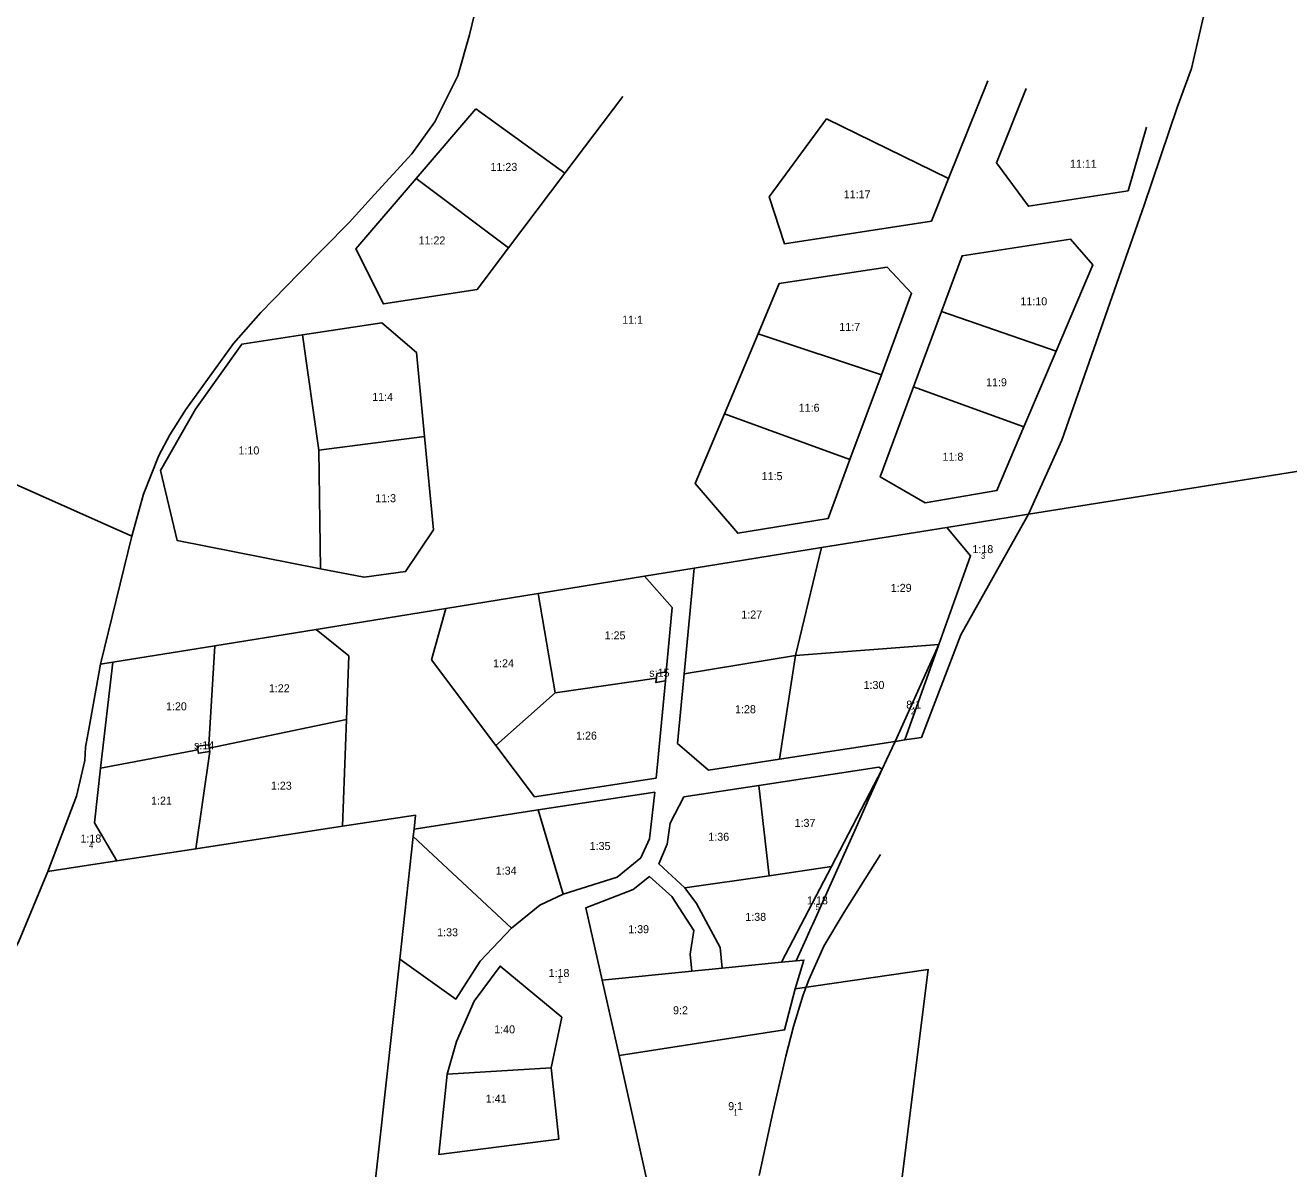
# Model space of a CAD drawing. Extents: x 140824 to 143748, y 6547319 to 6550906.
# Drawn here: x 142272 to 142825, y 6549186 to 6549686 of the extents above; entities that cross this region are included whole.
import ezdxf

# ---------------------------------------------------------------- set-up
doc = ezdxf.new("R2010")
doc.units = 0
for name, color, linetype in [('FAST Fastighetsgräns', 7, 'Continuous'), ('FAST Mittlinjeredovisad samfällighet', 7, 'Continuous'), ('FAST Områdesnummer för fastighet', 7, 'Continuous'), ('FAST Registernummer för fastighet', 7, 'Continuous'), ('FAST Registernummer för samfällighet', 7, 'Continuous'), ('FAST Traktgräns', 7, 'Continuous')]:
    doc.layers.add(name, color=color, linetype=linetype)

msp = doc.modelspace()

# ---------------------------------------------------------------- linework, layer by layer
at = {"layer": 'FAST Fastighetsgräns'}
for p, q in [((142675.82, 6549619.05), (142692.96, 6549661.84)), ((142508.04, 6549621.45), (142533.31, 6549654.96)), ((142469, 6549649.51), (142443, 6549619.12)), ((142469, 6549649.51), (142508.04, 6549621.45)), ((142622.4, 6549645.12), (142675.82, 6549619.05)), ((142483.42, 6549588.77), (142508.04, 6549621.45)), ((142443, 6549619.12), (142483.42, 6549588.77)), ((142672.7, 6549560.85), (142660.55, 6549527.94)), ((142672.7, 6549560.85), (142722.85, 6549543.49)), ((142400.45, 6549500.17), (142393.31, 6549550.62)), ((142592.5, 6549551.11), (142577.8, 6549516.08)), ((142592.5, 6549551.11), (142646.45, 6549533.24)), ((142708.8, 6549510.39), (142722.85, 6549543.49)), ((142632.71, 6549496.13), (142646.45, 6549533.24)), ((142660.55, 6549527.94), (142708.8, 6549510.39)), ((142577.8, 6549516.08), (142632.71, 6549496.13)), ((142446.62, 6549506.21), (142400.45, 6549500.17)), ((142400.45, 6549500.17), (142401.09, 6549448.37)), ((142675.03, 6549466.45), (142710.83, 6549472.25)), ((142620.32, 6549457.6), (142675.03, 6549466.45)), ((142564.58, 6549448.57), (142620.32, 6549457.6)), ((142620.32, 6549457.6), (142608.93, 6549410.36)), ((142496.26, 6549437.52), (142542.85, 6549445.06)), ((142542.85, 6549445.06), (142564.58, 6549448.57)), ((142564.58, 6549448.57), (142560.21, 6549402.42)), ((142455.97, 6549431.01), (142496.26, 6549437.52)), ((142496.26, 6549437.52), (142503.8, 6549394.01)), ((142399.21, 6549421.82), (142455.97, 6549431.01)), ((142354.84, 6549414.65), (142399.21, 6549421.82)), ((142310.22, 6549407.43), (142354.84, 6549414.65)), ((142354.84, 6549414.65), (142352.21, 6549371.35)), ((142608.93, 6549410.36), (142560.21, 6549402.42)), ((142601.88, 6549365.05), (142608.93, 6549410.36)), ((142671.55, 6549415.24), (142608.93, 6549410.36)), ((142652.51, 6549372.82), (142671.55, 6549415.24)), ((142656.76, 6549373.47), (142671.55, 6549415.24)), ((142304.88, 6549406.56), (142310.22, 6549407.43)), ((142304.93, 6549361.08), (142310.22, 6549407.43)), ((142548.06, 6549400.52), (142503.8, 6549394.01)), ((142547.92, 6549356.78), (142551.95, 6549399.26)), ((142552.33, 6549403.25), (142551.95, 6549399.26)), ((142503.8, 6549394.01), (142477.87, 6549370.99)), ((142352.43, 6549369.9), (142412.5, 6549382.47)), ((142412.5, 6549382.47), (142410.8, 6549335.74)), ((142352.21, 6549371.35), (142352.43, 6549369.9)), ((142601.88, 6549365.05), (142652.51, 6549372.82)), ((142304.93, 6549361.08), (142347.47, 6549369.18)), ((142352.65, 6549368.42), (142346.54, 6549325.89)), ((142352.43, 6549369.9), (142352.65, 6549368.42)), ((142494.7, 6549348.62), (142477.87, 6549370.99)), ((142570.83, 6549360.29), (142601.88, 6549365.05)), ((142646.84, 6549360.76), (142624.6, 6549318.05)), ((142494.7, 6549348.62), (142547.92, 6549356.78)), ((142597.4, 6549314.06), (142592.87, 6549353.55)), ((142410.8, 6549335.74), (142442.73, 6549340.63)), ((142442.06, 6549334.49), (142496.3, 6549342.96)), ((142442.73, 6549340.63), (142442.06, 6549334.49)), ((142496.3, 6549342.96), (142507.25, 6549306.05)), ((142346.54, 6549325.89), (142410.8, 6549335.74)), ((142442.06, 6549334.49), (142441.7, 6549331.2)), ((142441.7, 6549331.2), (142435.77, 6549277.57)), ((142484.67, 6549291.08), (142441.7, 6549331.2)), ((142312.03, 6549320.6), (142346.54, 6549325.89)), ((142597.4, 6549314.06), (142624.6, 6549318.05)), ((142624.6, 6549318.05), (142602.82, 6549276.22)), ((142560.47, 6549308.72), (142597.4, 6549314.06)), ((142501.98, 6549230.08), (142456.45, 6549227.35)), ((142456.45, 6549227.35), (142452.85, 6549192.17))]:
    msp.add_line(p, q, dxfattribs=at)
for points in [[(142805.51, 6549779.3), (142795.33, 6549724.78), (142782.15, 6549667.23), (142775.86, 6549650.05), (142761.34, 6549607.35), (142725.32, 6549504.57), (142710.83, 6549472.25)], [(142762.44, 6549641.48), (142754.38, 6549613.67), (142710.77, 6549606.89), (142696.76, 6549625.85), (142709.79, 6549658.38)], [(142675.82, 6549619.05), (142668.31, 6549600.32), (142604.03, 6549590.52), (142597.38, 6549610.97), (142622.4, 6549645.12)], [(142483.42, 6549588.77), (142469.59, 6549570.44), (142428.6, 6549564.17), (142416.58, 6549588.26), (142443, 6549619.12)], [(142722.85, 6549543.49), (142738.88, 6549581.22), (142729.23, 6549592.48), (142681.73, 6549585.27), (142672.7, 6549560.85)], [(142646.45, 6549533.24), (142659.65, 6549568.89), (142648.98, 6549580.27), (142601.73, 6549573.07), (142592.5, 6549551.11)], [(142393.31, 6549550.62), (142427.87, 6549555.94), (142443.06, 6549543.01), (142446.62, 6549506.21)], [(142331.15, 6549491.38), (142346.37, 6549518.14), (142366.64, 6549546.57), (142393.31, 6549550.62)], [(142708.8, 6549510.39), (142697, 6549482.58), (142665.56, 6549477.24), (142645.98, 6549488.53), (142660.55, 6549527.94)], [(142632.71, 6549496.13), (142623.15, 6549470.33), (142583.6, 6549463.88), (142565.05, 6549485.71), (142577.8, 6549516.08)], [(142446.62, 6549506.21), (142450.56, 6549465.34), (142438.3, 6549447.14), (142420.17, 6549444.62), (142401.09, 6549448.37)], [(142401.09, 6549448.37), (142338.42, 6549460.7), (142331.15, 6549491.38)], [(142675.03, 6549466.45), (142685.47, 6549453.99), (142671.55, 6549415.24)], [(142552.33, 6549403.25), (142555, 6549431.39), (142542.85, 6549445.06)], [(142477.87, 6549370.99), (142449.66, 6549408.48), (142455.97, 6549431.01)], [(142399.21, 6549421.82), (142413.51, 6549410.22), (142412.5, 6549382.47)], [(142551.95, 6549399.26), (142547.86, 6549398.53), (142548.06, 6549400.52)], [(142548.06, 6549400.52), (142548.24, 6549402.53), (142552.33, 6549403.25)], [(142560.21, 6549402.42), (142557.32, 6549371.92), (142570.83, 6549360.29)], [(142347.47, 6549369.18), (142347.17, 6549370.69), (142352.21, 6549371.35)], [(142352.65, 6549368.42), (142347.68, 6549367.65), (142347.47, 6549369.18)], [(142312.03, 6549320.6), (142302.2, 6549337.18), (142304.93, 6549361.08)], [(142592.87, 6549353.55), (142645.32, 6549361.6), (142646.84, 6549360.76)], [(142496.3, 6549342.96), (142547.29, 6549350.61), (142545.01, 6549330.21), (142541.28, 6549321.91), (142530.87, 6549313.41), (142507.25, 6549306.05)], [(142592.87, 6549353.55), (142560.08, 6549348.53), (142554.13, 6549337.13), (142552.68, 6549327.84), (142549.16, 6549319.33), (142560.47, 6549308.72)], [(142281.87, 6549315.97), (142286.33, 6549316.66), (142312.03, 6549320.6)], [(142524.28, 6549268.34), (142517.16, 6549299.97), (142537.9, 6549308.03), (142544.96, 6549313.72), (142554.8, 6549304.98), (142564.38, 6549290.1), (142562.82, 6549279.73), (142563.53, 6549272.28)], [(142507.25, 6549306.05), (142497.07, 6549301.23), (142484.67, 6549291.08)], [(142560.47, 6549308.72), (142565.55, 6549301.97), (142575.89, 6549282.72), (142576.75, 6549273.6)], [(142435.77, 6549277.57), (142460.25, 6549260.11), (142471.01, 6549276.69), (142484.67, 6549291.08)], [(142435.77, 6549277.57), (142423.51, 6549166.73), (142406.77, 6549013.95)], [(142456.45, 6549227.35), (142460.59, 6549241.58), (142468.34, 6549259.15), (142479.65, 6549274.56), (142506.68, 6549252.21), (142501.98, 6549230.08)], [(142608.76, 6549264.58), (142612.55, 6549277.2), (142609.25, 6549276.87)], [(142608.76, 6549264.58), (142666.93, 6549273.04), (142655.13, 6549178.85)], [(142531.74, 6549235.51), (142604.14, 6549246.64), (142608.76, 6549264.58)], [(142452.85, 6549192.17), (142505.33, 6549198.82), (142501.98, 6549230.08)]]:
    msp.add_lwpolyline(points, dxfattribs=at)
at = {"layer": 'FAST Mittlinjeredovisad samfällighet'}
msp.add_lwpolyline([(142592.97, 6549182.99), (142598.97, 6549210.46), (142604.69, 6549235.17), (142608.08, 6549248.17), (142612.19, 6549262.02), (142614.67, 6549268.55), (142621.26, 6549283.34), (142630.19, 6549298.2), (142646.06, 6549323.43)], dxfattribs=at)
at = {"layer": 'FAST Traktgräns'}
for p, q in [((142710.83, 6549472.25), (143747.82, 6549636.79)), ((142681.14, 6549419.48), (142710.83, 6549472.25)), ((142318.55, 6549462.6), (142304.88, 6549406.56)), ((142652.51, 6549372.82), (142652.66, 6549372.84)), ((142652.66, 6549372.84), (142656.76, 6549373.47)), ((142563.53, 6549272.28), (142524.28, 6549268.34)), ((142576.75, 6549273.6), (142563.53, 6549272.28)), ((142602.82, 6549276.22), (142576.75, 6549273.6)), ((142609.25, 6549276.87), (142602.82, 6549276.22)), ((142524.28, 6549268.34), (142531.74, 6549235.51))]:
    msp.add_line(p, q, dxfattribs=at)
for points in [[(142363.06, 6549546.88), (142375, 6549560.49), (142391.7, 6549577.52), (142413.6, 6549599.86), (142424.69, 6549612), (142441.02, 6549629.85), (142451.17, 6549643.83), (142461.25, 6549664.03), (142466.28, 6549681.83), (142470.59, 6549700.12), (142475.66, 6549711.87), (142480.66, 6549720.04), (142490.77, 6549731.81)], [(142330.4, 6549497.93), (142335.18, 6549506.86), (142342.18, 6549518.03), (142363.06, 6549546.88)], [(141669.62, 6549140.14), (142146.68, 6549539.12), (142318.55, 6549462.6)], [(142318.55, 6549462.6), (142323.72, 6549481.01), (142330.4, 6549497.93)], [(142656.76, 6549373.47), (142663.93, 6549374.57), (142681.14, 6549419.48)], [(142304.88, 6549406.56), (142299.76, 6549378.23), (142298.33, 6549370.33), (142298.09, 6549364.49), (142294.45, 6549348.94), (142281.87, 6549315.97)], [(142652.51, 6549372.82), (142648.72, 6549364.76), (142646.84, 6549360.76)], [(142646.84, 6549360.76), (142641.29, 6549348.48), (142635.37, 6549335.24), (142631.45, 6549326.48), (142623.16, 6549307.92), (142619.48, 6549299.68), (142616.46, 6549292.94), (142615.64, 6549291.1), (142613.59, 6549286.53), (142609.25, 6549276.87)], [(142281.87, 6549315.97), (142269.02, 6549284.98), (142216.86, 6549191.14), (142160.87, 6549100.73), (142129.44, 6549008.95)], [(142579.08, 6549169.29), (142547.42, 6549165.22), (142531.74, 6549235.51)]]:
    msp.add_lwpolyline(points, dxfattribs=at)

# ---------------------------------------------------------------- texts
at = {"layer": 'FAST Områdesnummer för fastighet'}
for s, p in [('3', (142690.03, 6549452.68)), ('2', (142659.39, 6549384.68)), ('4', (142299.88, 6549326.11)), ('5', (142617.66, 6549299.05)), ('1', (142504.88, 6549267.28)), ('1', (142581.74, 6549209.06))]:
    msp.add_text(s, height=2.5, dxfattribs=at).set_placement(p)
at = {"layer": 'FAST Registernummer för fastighet'}
for s, p in [('11:23', (142475.47, 6549622.38)), ('11:11', (142728.95, 6549623.74)), ('11:17', (142629.98, 6549610.39)), ('11:22', (142444, 6549590.22)), ('11:10', (142707.28, 6549563.59)), ('11:1', (142533.06, 6549555.54)), ('11:7', (142628.05, 6549552.41)), ('11:9', (142692.25, 6549528.17)), ('11:4', (142423.74, 6549521.78)), ('11:6', (142610.29, 6549517.03)), ('1:10', (142365.24, 6549498.36)), ('11:8', (142673.2, 6549495.6)), ('11:5', (142594.08, 6549487.13)), ('11:3', (142425.04, 6549477.47)), ('1:18', (142686.27, 6549455.18)), ('1:29', (142650.57, 6549438.25)), ('1:27', (142585.19, 6549426.57)), ('1:25', (142525.4, 6549417.47)), ('1:24', (142476.62, 6549405.25)), ('1:30', (142638.66, 6549395.77)), ('1:22', (142378.53, 6549394.32)), ('1:20', (142333.54, 6549386.43)), ('1:28', (142582.44, 6549385.17)), ('8:1', (142657.32, 6549387.18)), ('1:26', (142512.91, 6549373.62)), ('1:23', (142379.42, 6549351.73)), ('1:21', (142326.99, 6549345.17)), ('1:37', (142608.49, 6549335.45)), ('1:36', (142570.76, 6549329.38)), ('1:18', (142296.12, 6549328.61)), ('1:35', (142518.85, 6549325.34)), ('1:34', (142477.76, 6549314.56)), ('1:18', (142613.91, 6549301.55)), ('1:38', (142586.93, 6549294.34)), ('1:33', (142452.15, 6549287.6)), ('1:39', (142535.71, 6549288.95)), ('1:18', (142500.88, 6549269.78)), ('9:2', (142555.33, 6549253.5)), ('1:40', (142477.09, 6549245.14)), ('1:41', (142473.38, 6549214.82)), ('9:1', (142579.44, 6549211.56))]:
    msp.add_text(s, height=3.5, dxfattribs=at).set_placement(p)
at = {"layer": 'FAST Registernummer för samfällighet'}
for s, p in [('s:15', (142544.92, 6549401.11)), ('s:14', (142345.81, 6549369.41))]:
    msp.add_text(s, height=3.5, dxfattribs=at).set_placement(p)

doc.saveas('drawing.dxf')
